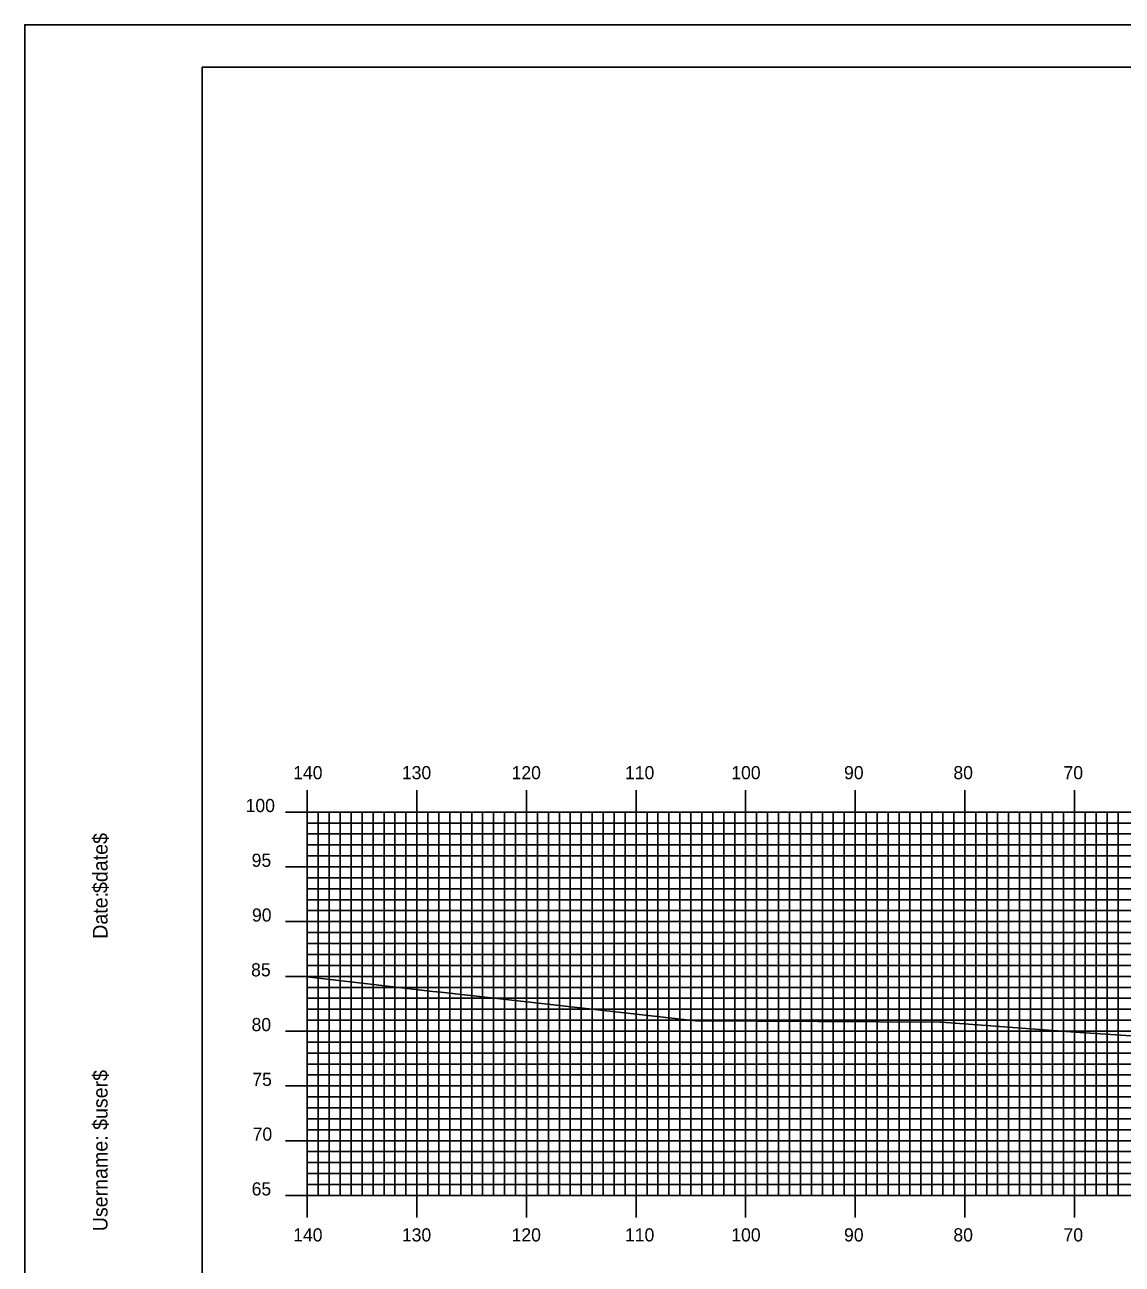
# Model space of a CAD drawing. Extents: x 1775957 to 1776301, y 442591 to 442811.
# Drawn here: x 1775957.4 to 1776057.6, y 442697.4 to 442810.5 of the extents above; entities that cross this region are included whole.
import ezdxf

# ---------------------------------------------------------------- set-up
doc = ezdxf.new("R2010")
doc.units = 0
for name, color, linetype in [('BORDER', 7, 'Continuous'), ('H_V ANNOTATION', 7, 'Continuous'), ('MAJOR', 7, 'Continuous'), ('MINOR', 7, 'Continuous'), ('PLOT BOUNDARY', 7, 'Continuous'), ('S_Roadway_Centerline', 7, 'Continuous')]:
    doc.layers.add(name, color=color, linetype=linetype)

msp = doc.modelspace()

# ---------------------------------------------------------------- linework, layer by layer
at = {"layer": 'BORDER'}
msp.add_lwpolyline([(1775973.62, 442596.67), (1776293.62, 442596.67), (1776293.62, 442806.67), (1775973.62, 442806.67)], close=True, dxfattribs=at)
at = {"layer": 'MAJOR'}
for p, q in [((1775983.22, 442740.67), (1775983.22, 442738.67)), ((1775993.22, 442740.67), (1775993.22, 442738.67)), ((1776003.22, 442740.67), (1776003.22, 442738.67)), ((1776013.22, 442740.67), (1776013.22, 442738.67)), ((1776023.22, 442740.67), (1776023.22, 442738.67)), ((1776033.22, 442740.67), (1776033.22, 442738.67)), ((1776043.22, 442740.67), (1776043.22, 442738.67)), ((1776053.22, 442740.67), (1776053.22, 442738.67)), ((1775981.22, 442738.67), (1775983.22, 442738.67)), ((1775983.22, 442738.67), (1776263.22, 442738.67)), ((1775983.22, 442703.67), (1775983.22, 442738.67)), ((1775983.22, 442703.67), (1775983.22, 442738.67)), ((1775983.22, 442738.67), (1776263.22, 442738.67)), ((1775993.22, 442703.67), (1775993.22, 442738.67)), ((1776003.22, 442703.67), (1776003.22, 442738.67)), ((1776013.22, 442703.67), (1776013.22, 442738.67)), ((1776023.22, 442703.67), (1776023.22, 442738.67)), ((1776033.22, 442703.67), (1776033.22, 442738.67)), ((1776043.22, 442703.67), (1776043.22, 442738.67)), ((1776053.22, 442703.67), (1776053.22, 442738.67)), ((1775981.22, 442733.67), (1775983.22, 442733.67)), ((1775983.22, 442733.67), (1776263.22, 442733.67)), ((1775981.22, 442728.67), (1775983.22, 442728.67)), ((1775983.22, 442728.67), (1776263.22, 442728.67)), ((1775981.22, 442723.67), (1775983.22, 442723.67)), ((1775983.22, 442723.67), (1776263.22, 442723.67)), ((1775981.22, 442718.67), (1775983.22, 442718.67)), ((1775983.22, 442718.67), (1776263.22, 442718.67)), ((1775981.22, 442713.67), (1775983.22, 442713.67)), ((1775983.22, 442713.67), (1776263.22, 442713.67)), ((1775981.22, 442708.67), (1775983.22, 442708.67)), ((1775983.22, 442708.67), (1776263.22, 442708.67)), ((1775981.22, 442703.67), (1775983.22, 442703.67)), ((1775983.22, 442703.67), (1776263.22, 442703.67)), ((1775983.22, 442703.67), (1776263.22, 442703.67)), ((1775983.22, 442701.66), (1775983.22, 442703.67)), ((1775993.22, 442701.66), (1775993.22, 442703.67)), ((1776003.22, 442701.66), (1776003.22, 442703.67)), ((1776013.22, 442701.66), (1776013.22, 442703.67)), ((1776023.22, 442701.66), (1776023.22, 442703.67)), ((1776033.22, 442701.66), (1776033.22, 442703.67)), ((1776043.22, 442701.66), (1776043.22, 442703.67)), ((1776053.22, 442701.66), (1776053.22, 442703.67))]:
    msp.add_line(p, q, dxfattribs=at)
at = {"layer": 'MINOR'}
for p, q in [((1775983.22, 442737.67), (1776263.22, 442737.67)), ((1775983.22, 442737.67), (1775985.23, 442737.67)), ((1775984.22, 442703.67), (1775984.22, 442738.67)), ((1775985.22, 442703.67), (1775985.22, 442738.67)), ((1775986.22, 442703.67), (1775986.22, 442738.67)), ((1775987.22, 442703.67), (1775987.22, 442738.67)), ((1775988.22, 442703.67), (1775988.22, 442738.67)), ((1775989.22, 442703.67), (1775989.22, 442738.67)), ((1775990.22, 442703.67), (1775990.22, 442738.67)), ((1775991.22, 442703.67), (1775991.22, 442738.67)), ((1775992.22, 442703.67), (1775992.22, 442738.67)), ((1775994.22, 442703.67), (1775994.22, 442738.67)), ((1775995.22, 442703.67), (1775995.22, 442738.67)), ((1775996.22, 442703.67), (1775996.22, 442738.67)), ((1775997.22, 442703.67), (1775997.22, 442738.67)), ((1775998.22, 442703.67), (1775998.22, 442738.67)), ((1775999.22, 442703.67), (1775999.22, 442738.67)), ((1776000.22, 442703.67), (1776000.22, 442738.67)), ((1776001.22, 442703.67), (1776001.22, 442738.67)), ((1776002.22, 442703.67), (1776002.22, 442738.67)), ((1776004.22, 442703.67), (1776004.22, 442738.67)), ((1776005.22, 442703.67), (1776005.22, 442738.67)), ((1776006.22, 442703.67), (1776006.22, 442738.67)), ((1776007.22, 442703.67), (1776007.22, 442738.67)), ((1776008.22, 442703.67), (1776008.22, 442738.67)), ((1776009.22, 442703.67), (1776009.22, 442738.67)), ((1776010.22, 442703.67), (1776010.22, 442738.67)), ((1776011.22, 442703.67), (1776011.22, 442738.67)), ((1776012.22, 442703.67), (1776012.22, 442738.67)), ((1776014.22, 442703.67), (1776014.22, 442738.67)), ((1776015.22, 442703.67), (1776015.22, 442738.67)), ((1776016.22, 442703.67), (1776016.22, 442738.67)), ((1776017.22, 442703.67), (1776017.22, 442738.67)), ((1776018.22, 442703.67), (1776018.22, 442738.67)), ((1776019.22, 442703.67), (1776019.22, 442738.67)), ((1776020.22, 442703.67), (1776020.22, 442738.67)), ((1776021.22, 442703.67), (1776021.22, 442738.67)), ((1776022.22, 442703.67), (1776022.22, 442738.67)), ((1776024.22, 442703.67), (1776024.22, 442738.67)), ((1776025.22, 442703.67), (1776025.22, 442738.67)), ((1776026.22, 442703.67), (1776026.22, 442738.67)), ((1776027.22, 442703.67), (1776027.22, 442738.67)), ((1776028.22, 442703.67), (1776028.22, 442738.67)), ((1776029.22, 442703.67), (1776029.22, 442738.67)), ((1776030.22, 442703.67), (1776030.22, 442738.67)), ((1776031.22, 442703.67), (1776031.22, 442738.67)), ((1776032.22, 442703.67), (1776032.22, 442738.67)), ((1776034.22, 442703.67), (1776034.22, 442738.67)), ((1776035.22, 442703.67), (1776035.22, 442738.67)), ((1776036.22, 442703.67), (1776036.22, 442738.67)), ((1776037.22, 442703.67), (1776037.22, 442738.67)), ((1776038.22, 442703.67), (1776038.22, 442738.67)), ((1776039.22, 442703.67), (1776039.22, 442738.67)), ((1776040.22, 442703.67), (1776040.22, 442738.67)), ((1776041.22, 442703.67), (1776041.22, 442738.67)), ((1776042.22, 442703.67), (1776042.22, 442738.67)), ((1776044.22, 442703.67), (1776044.22, 442738.67)), ((1776045.22, 442703.67), (1776045.22, 442738.67)), ((1776046.22, 442703.67), (1776046.22, 442738.67)), ((1776047.22, 442703.67), (1776047.22, 442738.67)), ((1776048.22, 442703.67), (1776048.22, 442738.67)), ((1776049.22, 442703.67), (1776049.22, 442738.67)), ((1776050.22, 442703.67), (1776050.22, 442738.67)), ((1776051.22, 442703.67), (1776051.22, 442738.67)), ((1776052.22, 442703.67), (1776052.22, 442738.67)), ((1776054.22, 442703.67), (1776054.22, 442738.67)), ((1776055.22, 442703.67), (1776055.22, 442738.67)), ((1776056.22, 442703.67), (1776056.22, 442738.67)), ((1776057.22, 442703.67), (1776057.22, 442738.67)), ((1775983.22, 442736.67), (1776263.22, 442736.67)), ((1775983.22, 442736.67), (1775985.23, 442736.67)), ((1775983.22, 442735.67), (1776263.22, 442735.67)), ((1775983.22, 442735.67), (1775985.23, 442735.67)), ((1775983.22, 442734.67), (1776263.22, 442734.67)), ((1775983.22, 442734.67), (1775985.23, 442734.67)), ((1775983.22, 442732.67), (1776263.22, 442732.67)), ((1775983.22, 442732.67), (1775985.23, 442732.67)), ((1775983.22, 442731.67), (1776263.22, 442731.67)), ((1775983.22, 442731.67), (1775985.23, 442731.67)), ((1775983.22, 442730.67), (1776263.22, 442730.67)), ((1775983.22, 442730.67), (1775985.23, 442730.67)), ((1775983.22, 442729.67), (1776263.22, 442729.67)), ((1775983.22, 442729.67), (1775985.23, 442729.67)), ((1775983.22, 442727.67), (1776263.22, 442727.67)), ((1775983.22, 442727.67), (1775985.23, 442727.67)), ((1775983.22, 442726.67), (1776263.22, 442726.67)), ((1775983.22, 442726.67), (1775985.23, 442726.67)), ((1775983.22, 442725.67), (1776263.22, 442725.67)), ((1775983.22, 442725.67), (1775985.23, 442725.67)), ((1775983.22, 442724.67), (1776263.22, 442724.67)), ((1775983.22, 442724.67), (1775985.23, 442724.67)), ((1775983.22, 442722.67), (1776263.22, 442722.67)), ((1775983.22, 442722.67), (1775985.23, 442722.67)), ((1775983.22, 442721.67), (1776263.22, 442721.67)), ((1775983.22, 442721.67), (1775985.23, 442721.67)), ((1775983.22, 442720.67), (1776263.22, 442720.67)), ((1775983.22, 442720.67), (1775985.23, 442720.67)), ((1775983.22, 442719.67), (1776263.22, 442719.67)), ((1775983.22, 442719.67), (1775985.23, 442719.67)), ((1775983.22, 442717.67), (1776263.22, 442717.67)), ((1775983.22, 442717.67), (1775985.23, 442717.67)), ((1775983.22, 442716.67), (1776263.22, 442716.67)), ((1775983.22, 442716.67), (1775985.23, 442716.67)), ((1775983.22, 442715.67), (1776263.22, 442715.67)), ((1775983.22, 442715.67), (1775985.23, 442715.67)), ((1775983.22, 442714.67), (1776263.22, 442714.67)), ((1775983.22, 442714.67), (1775985.23, 442714.67)), ((1775983.22, 442712.67), (1776263.22, 442712.67)), ((1775983.22, 442712.67), (1775985.23, 442712.67)), ((1775983.22, 442711.67), (1776263.22, 442711.67)), ((1775983.22, 442711.67), (1775985.23, 442711.67)), ((1775983.22, 442710.67), (1776263.22, 442710.67)), ((1775983.22, 442710.67), (1775985.23, 442710.67)), ((1775983.22, 442709.67), (1776263.22, 442709.67)), ((1775983.22, 442709.67), (1775985.23, 442709.67)), ((1775983.22, 442707.67), (1776263.22, 442707.67)), ((1775983.22, 442707.67), (1775985.23, 442707.67)), ((1775983.22, 442706.67), (1776263.22, 442706.67)), ((1775983.22, 442706.67), (1775985.23, 442706.67)), ((1775983.22, 442705.67), (1776263.22, 442705.67)), ((1775983.22, 442705.67), (1775985.23, 442705.67)), ((1775983.22, 442704.67), (1776263.22, 442704.67)), ((1775983.22, 442704.67), (1775985.23, 442704.67))]:
    msp.add_line(p, q, dxfattribs=at)
at = {"layer": 'PLOT BOUNDARY'}
msp.add_lwpolyline([(1775957.44, 442590.55), (1776297.44, 442590.55), (1776297.44, 442810.55), (1775957.44, 442810.55)], close=True, dxfattribs=at)
at = {"layer": 'S_Roadway_Centerline'}
msp.add_lwpolyline([(1775983.22, 442723.62), (1775988.72, 442723), (1775994.68, 442722.3), (1775995.39, 442722.22), (1776017.02, 442719.78), (1776018.64, 442719.6), (1776018.66, 442719.6), (1776040.97, 442719.49), (1776041.11, 442719.48), (1776053.29, 442718.58), (1776063.47, 442717.9)], dxfattribs=at)

# ---------------------------------------------------------------- texts
at = {"layer": 'BORDER'}
for s, p in [('$date$', (1775964.99, 442731.28)), ('Date:', (1775964.99, 442727.1)), ('$user$', (1775964.99, 442709.65)), ('Username:', (1775964.99, 442700.4))]:
    msp.add_text(s, height=1.339, rotation=90, dxfattribs=at).set_placement(p)
at = {"layer": 'H_V ANNOTATION'}
for s, p in [('140', (1775981.93, 442741.67)), ('130', (1775991.85, 442741.67)), ('120', (1776001.86, 442741.67)), ('110', (1776012.21, 442741.67)), ('100', (1776021.91, 442741.67)), ('90', (1776032.2, 442741.67)), ('80', (1776042.18, 442741.67)), ('70', (1776052.23, 442741.67)), ('100', (1775977.59, 442738.67)), ('95', (1775978.14, 442733.67)), ('90', (1775978.17, 442728.67)), ('85', (1775978.09, 442723.67)), ('80', (1775978.13, 442718.67)), ('75', (1775978.2, 442713.67)), ('70', (1775978.23, 442708.67)), ('65', (1775978.14, 442703.67)), ('140', (1775981.93, 442699.47)), ('130', (1775991.85, 442699.47)), ('120', (1776001.86, 442699.47)), ('110', (1776012.21, 442699.47)), ('100', (1776021.91, 442699.47)), ('90', (1776032.2, 442699.47)), ('80', (1776042.18, 442699.47)), ('70', (1776052.23, 442699.47))]:
    msp.add_text(s, height=1.2, dxfattribs=at).set_placement(p)
at = {"layer": 'MAJOR'}
msp.add_text('-', height=0.012, dxfattribs=at).set_placement((1775983.22, 442703.67))

doc.saveas('drawing.dxf')
